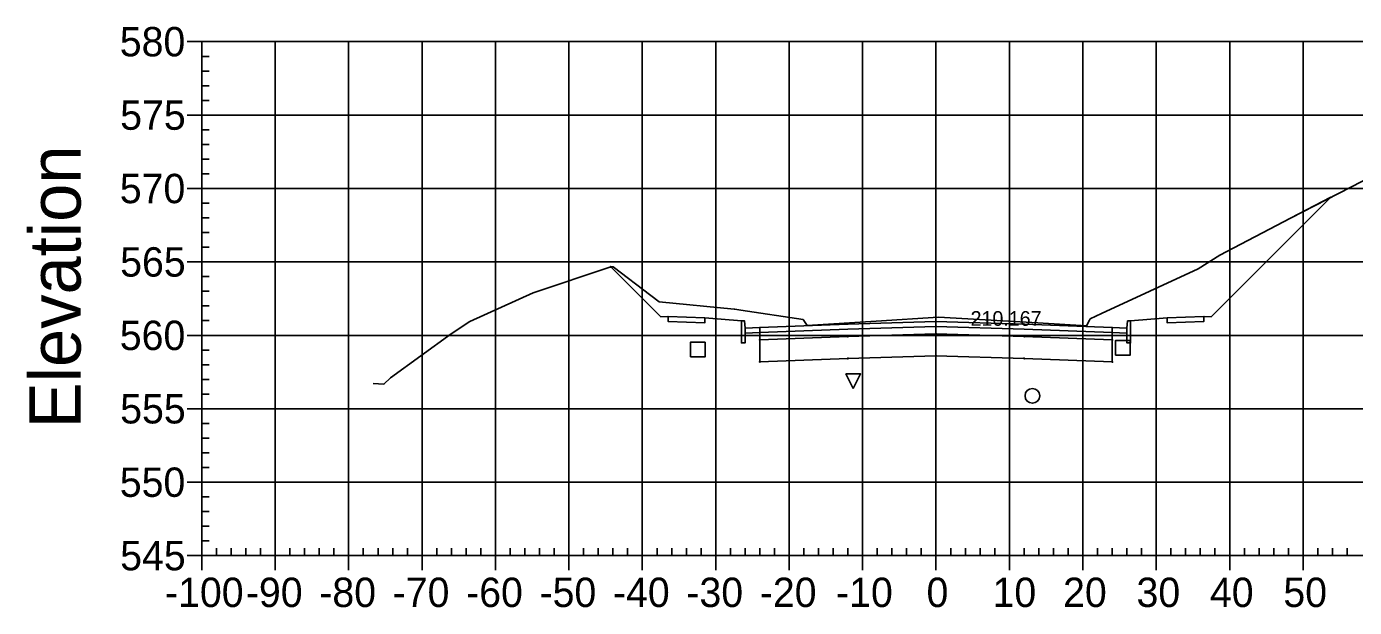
# Model space of a CAD drawing. Extents: x 704834 to 709892, y 372981 to 377533.
# Drawn here: x 706563 to 706743.9, y 373685.8 to 373764.9 of the extents above; entities that cross this region are included whole.
import ezdxf

# ---------------------------------------------------------------- set-up
doc = ezdxf.new("R2010")
doc.units = 0
for name, color, linetype in [('1', 7, 'Continuous'), ('10', 7, 'Continuous'), ('13', 7, 'Continuous'), ('14', 7, 'Continuous'), ('4', 7, 'Continuous'), ('57', 7, 'Continuous'), ('59', 7, 'Continuous'), ('60', 7, 'Continuous'), ('Default_Xsect', 7, 'Continuous'), ('Existing', 7, 'Continuous')]:
    doc.layers.add(name, color=color, linetype=linetype)

msp = doc.modelspace()

# ---------------------------------------------------------------- linework, layer by layer
for points in [[(706724.37, 373725.35), (706740.65, 373741.62)], [(706649.37, 373725.35), (706642.57, 373732.15)], [(706650.37, 373725.39), (706649.37, 373725.35)], [(706660.37, 373724.79), (706655.37, 373725.19)], [(706713.37, 373724.79), (706718.37, 373725.19)], [(706723.37, 373725.39), (706724.37, 373725.35)]]:
    msp.add_lwpolyline(points)
for points in [[(706655.37, 373725.19), (706650.37, 373725.39), (706650.37, 373724.72), (706655.37, 373724.52)], [(706718.37, 373724.52), (706723.37, 373724.72), (706723.37, 373725.39), (706718.37, 373725.19)], [(706660.87, 373723.79), (706660.79, 373724.79), (706660.37, 373724.79), (706660.37, 373721.79), (706660.87, 373721.79)], [(706662.87, 373723.87), (706660.87, 373723.79), (706660.87, 373723.12), (706662.87, 373723.2)], [(706686.87, 373724.04), (706698.87, 373723.68), (706710.87, 373723.2), (706710.87, 373723.87), (706698.87, 373724.35), (706686.87, 373724.71), (706674.87, 373724.35), (706662.87, 373723.87), (706662.87, 373723.2), (706674.87, 373723.68)], [(706686.87, 373723.04), (706698.87, 373722.68), (706710.87, 373722.2), (706710.87, 373723.2), (706698.87, 373723.68), (706686.87, 373724.04), (706674.87, 373723.68), (706662.87, 373723.2), (706662.87, 373722.2), (706674.87, 373722.68)], [(706686.82, 373723.99), (706686.92, 373723.99), (706686.92, 373724.09), (706686.82, 373724.09)], [(706710.87, 373723.2), (706712.87, 373723.12), (706712.87, 373723.79), (706710.87, 373723.87)], [(706712.87, 373721.79), (706713.37, 373721.79), (706713.37, 373724.79), (706712.96, 373724.79), (706712.87, 373723.79)], [(706662.82, 373722.15), (706662.92, 373722.15), (706662.92, 373722.25), (706662.82, 373722.25)], [(706686.87, 373720.04), (706698.87, 373719.68), (706710.87, 373719.2), (706710.87, 373722.2), (706698.87, 373722.68), (706686.87, 373723.04), (706674.87, 373722.68), (706662.87, 373722.2), (706662.87, 373719.2), (706674.87, 373719.68)], [(706674.82, 373722.63), (706674.92, 373722.63), (706674.92, 373722.73), (706674.82, 373722.73)], [(706686.82, 373722.99), (706686.92, 373722.99), (706686.92, 373723.09), (706686.82, 373723.09)], [(706698.82, 373722.63), (706698.92, 373722.63), (706698.92, 373722.73), (706698.82, 373722.73)], [(706710.82, 373722.15), (706710.92, 373722.15), (706710.92, 373722.25), (706710.82, 373722.25)], [(706674.82, 373719.63), (706674.92, 373719.63), (706674.92, 373719.73), (706674.82, 373719.73)], [(706686.82, 373719.99), (706686.92, 373719.99), (706686.92, 373720.09), (706686.82, 373720.09)], [(706698.82, 373719.63), (706698.92, 373719.63), (706698.92, 373719.73), (706698.82, 373719.73)], [(706662.82, 373719.15), (706662.92, 373719.15), (706662.92, 373719.25), (706662.82, 373719.25)], [(706710.82, 373719.15), (706710.92, 373719.15), (706710.92, 373719.25), (706710.82, 373719.25)]]:
    msp.add_lwpolyline(points, close=True)
at = {"layer": '1'}
for points in [[(706642.57, 373732.15), (706642.58, 373732.16), (706642.88, 373732.17), (706648.01, 373728.27), (706649.18, 373727.39), (706659.39, 373726.4), (706659.47, 373726.38), (706660.28, 373726.27), (706668.77, 373724.97), (706668.95, 373724.7), (706669.33, 373724.17), (706678.71, 373724.76), (706687.23, 373725.28), (706700.72, 373724.54), (706707.39, 373724.11), (706707.8, 373724.89), (706707.89, 373725.06), (706709.39, 373725.78), (706722.56, 373731.87), (706725.52, 373733.74), (706735.16, 373738.8), (706740.65, 373741.62), (706724.37, 373725.35), (706723.37, 373725.39), (706723.37, 373724.72), (706718.37, 373724.52), (706718.37, 373725.19), (706713.37, 373724.79), (706713.37, 373721.79), (706712.87, 373721.79), (706712.87, 373723.12), (706710.87, 373723.2), (706710.87, 373722.2), (706710.87, 373719.2), (706698.87, 373719.68), (706686.87, 373720.04), (706674.87, 373719.68), (706662.87, 373719.2), (706662.87, 373722.2), (706662.87, 373723.2), (706660.87, 373723.12), (706660.87, 373721.79), (706660.37, 373721.79), (706660.37, 373724.79), (706655.37, 373725.19), (706655.37, 373724.52), (706650.37, 373724.72), (706650.37, 373725.39), (706649.37, 373725.35)], [(706675.59, 373715.56), (706674.59, 373717.56), (706676.59, 373717.56)]]:
    msp.add_lwpolyline(points, close=True, dxfattribs=at)
at = {"layer": '10'}
msp.add_lwpolyline([(706653.42, 373719.88), (706655.42, 373719.88), (706655.42, 373721.88), (706653.42, 373721.88)], close=True, dxfattribs=at)
at = {"layer": '13'}
msp.add_circle((706700, 373714.58), 1, dxfattribs=at)
at = {"layer": '14'}
for points in [[(706740.65, 373741.62), (706740.65, 373741.67), (706740.65, 373741.62), (706740.6, 373741.62), (706740.65, 373741.62), (706740.65, 373741.57), (706740.65, 373741.62), (706740.7, 373741.62)], [(706642.57, 373732.15), (706642.57, 373732.2), (706642.57, 373732.15), (706642.52, 373732.15), (706642.57, 373732.15), (706642.57, 373732.1), (706642.57, 373732.15), (706642.62, 373732.15)], [(706662.87, 373723.87), (706662.87, 373723.92), (706662.87, 373723.87), (706662.82, 373723.87), (706662.87, 373723.87), (706662.87, 373723.82), (706662.87, 373723.87), (706662.92, 373723.87)], [(706674.87, 373724.35), (706674.87, 373724.4), (706674.87, 373724.35), (706674.82, 373724.35), (706674.87, 373724.35), (706674.87, 373724.3), (706674.87, 373724.35), (706674.92, 373724.35)], [(706686.87, 373724.71), (706686.87, 373724.76), (706686.87, 373724.71), (706686.82, 373724.71), (706686.87, 373724.71), (706686.87, 373724.66), (706686.87, 373724.71), (706686.92, 373724.71)], [(706698.87, 373724.35), (706698.87, 373724.4), (706698.87, 373724.35), (706698.82, 373724.35), (706698.87, 373724.35), (706698.87, 373724.3), (706698.87, 373724.35), (706698.92, 373724.35)], [(706710.87, 373723.87), (706710.87, 373723.92), (706710.87, 373723.87), (706710.82, 373723.87), (706710.87, 373723.87), (706710.87, 373723.82), (706710.87, 373723.87), (706710.92, 373723.87)]]:
    msp.add_lwpolyline(points, dxfattribs=at)
at = {"layer": '4'}
msp.add_lwpolyline([(706711.33, 373720.14), (706713.33, 373720.14), (706713.33, 373722.14), (706711.33, 373722.14)], close=True, dxfattribs=at)
at = {"layer": '57'}
for p, q in [((706584.87, 373762.82), (706586.87, 373762.82)), ((706586.87, 373762.82), (706786.87, 373762.82)), ((706586.87, 373692.82), (706586.87, 373762.82)), ((706586.87, 373692.82), (706586.87, 373762.82)), ((706596.87, 373692.82), (706596.87, 373762.82)), ((706606.87, 373692.82), (706606.87, 373762.82)), ((706616.87, 373692.82), (706616.87, 373762.82)), ((706626.87, 373692.82), (706626.87, 373762.82)), ((706636.87, 373692.82), (706636.87, 373762.82)), ((706646.87, 373692.82), (706646.87, 373762.82)), ((706656.87, 373692.82), (706656.87, 373762.82)), ((706666.87, 373692.82), (706666.87, 373762.82)), ((706676.87, 373692.82), (706676.87, 373762.82)), ((706686.87, 373692.82), (706686.87, 373762.82)), ((706696.87, 373692.82), (706696.87, 373762.82)), ((706706.87, 373692.82), (706706.87, 373762.82)), ((706716.87, 373692.82), (706716.87, 373762.82)), ((706726.87, 373692.82), (706726.87, 373762.82)), ((706736.87, 373692.82), (706736.87, 373762.82)), ((706586.87, 373760.82), (706587.87, 373760.82)), ((706586.87, 373758.82), (706587.87, 373758.82)), ((706586.87, 373756.82), (706587.87, 373756.82)), ((706586.87, 373754.82), (706587.87, 373754.82)), ((706584.87, 373752.82), (706586.87, 373752.82)), ((706586.87, 373752.82), (706786.87, 373752.82)), ((706586.87, 373750.82), (706587.87, 373750.82)), ((706586.87, 373748.82), (706587.87, 373748.82)), ((706586.87, 373746.82), (706587.87, 373746.82)), ((706586.87, 373744.82), (706587.87, 373744.82)), ((706584.87, 373742.82), (706586.87, 373742.82)), ((706586.87, 373742.82), (706786.87, 373742.82)), ((706586.87, 373740.82), (706587.87, 373740.82)), ((706586.87, 373738.82), (706587.87, 373738.82)), ((706586.87, 373736.82), (706587.87, 373736.82)), ((706586.87, 373734.82), (706587.87, 373734.82)), ((706584.87, 373732.82), (706586.87, 373732.82)), ((706586.87, 373732.82), (706786.87, 373732.82)), ((706586.87, 373730.82), (706587.87, 373730.82)), ((706586.87, 373728.82), (706587.87, 373728.82)), ((706586.87, 373726.82), (706587.87, 373726.82)), ((706586.87, 373724.82), (706587.87, 373724.82)), ((706584.87, 373722.82), (706586.87, 373722.82)), ((706586.87, 373722.82), (706786.87, 373722.82)), ((706586.87, 373720.82), (706587.87, 373720.82)), ((706586.87, 373718.82), (706587.87, 373718.82)), ((706586.87, 373716.82), (706587.87, 373716.82)), ((706586.87, 373714.82), (706587.87, 373714.82)), ((706584.87, 373712.82), (706586.87, 373712.82)), ((706586.87, 373712.82), (706786.87, 373712.82)), ((706586.87, 373710.82), (706587.87, 373710.82)), ((706586.87, 373708.82), (706587.87, 373708.82)), ((706586.87, 373706.82), (706587.87, 373706.82)), ((706586.87, 373704.82), (706587.87, 373704.82)), ((706584.87, 373702.82), (706586.87, 373702.82)), ((706586.87, 373702.82), (706786.87, 373702.82)), ((706586.87, 373700.82), (706587.87, 373700.82)), ((706586.87, 373698.82), (706587.87, 373698.82)), ((706586.87, 373696.82), (706587.87, 373696.82)), ((706586.87, 373694.82), (706587.87, 373694.82)), ((706584.87, 373692.82), (706586.87, 373692.82)), ((706586.87, 373692.82), (706786.87, 373692.82)), ((706586.87, 373692.82), (706786.87, 373692.82)), ((706586.87, 373690.82), (706586.87, 373692.82)), ((706588.87, 373692.82), (706588.87, 373693.82)), ((706590.87, 373692.82), (706590.87, 373693.82)), ((706592.87, 373692.82), (706592.87, 373693.82)), ((706594.87, 373692.82), (706594.87, 373693.82)), ((706596.87, 373690.82), (706596.87, 373692.82)), ((706598.87, 373692.82), (706598.87, 373693.82)), ((706600.87, 373692.82), (706600.87, 373693.82)), ((706602.87, 373692.82), (706602.87, 373693.82)), ((706604.87, 373692.82), (706604.87, 373693.82)), ((706606.87, 373690.82), (706606.87, 373692.82)), ((706608.87, 373692.82), (706608.87, 373693.82)), ((706610.87, 373692.82), (706610.87, 373693.82)), ((706612.87, 373692.82), (706612.87, 373693.82)), ((706614.87, 373692.82), (706614.87, 373693.82)), ((706616.87, 373690.82), (706616.87, 373692.82)), ((706618.87, 373692.82), (706618.87, 373693.82)), ((706620.87, 373692.82), (706620.87, 373693.82)), ((706622.87, 373692.82), (706622.87, 373693.82)), ((706624.87, 373692.82), (706624.87, 373693.82)), ((706626.87, 373690.82), (706626.87, 373692.82)), ((706628.87, 373692.82), (706628.87, 373693.82)), ((706630.87, 373692.82), (706630.87, 373693.82)), ((706632.87, 373692.82), (706632.87, 373693.82)), ((706634.87, 373692.82), (706634.87, 373693.82)), ((706636.87, 373690.82), (706636.87, 373692.82)), ((706638.87, 373692.82), (706638.87, 373693.82)), ((706640.87, 373692.82), (706640.87, 373693.82)), ((706642.87, 373692.82), (706642.87, 373693.82)), ((706644.87, 373692.82), (706644.87, 373693.82)), ((706646.87, 373690.82), (706646.87, 373692.82)), ((706648.87, 373692.82), (706648.87, 373693.82)), ((706650.87, 373692.82), (706650.87, 373693.82)), ((706652.87, 373692.82), (706652.87, 373693.82)), ((706654.87, 373692.82), (706654.87, 373693.82)), ((706656.87, 373690.82), (706656.87, 373692.82)), ((706658.87, 373692.82), (706658.87, 373693.82)), ((706660.87, 373692.82), (706660.87, 373693.82)), ((706662.87, 373692.82), (706662.87, 373693.82)), ((706664.87, 373692.82), (706664.87, 373693.82)), ((706666.87, 373690.82), (706666.87, 373692.82)), ((706668.87, 373692.82), (706668.87, 373693.82)), ((706670.87, 373692.82), (706670.87, 373693.82)), ((706672.87, 373692.82), (706672.87, 373693.82)), ((706674.87, 373692.82), (706674.87, 373693.82)), ((706676.87, 373690.82), (706676.87, 373692.82)), ((706678.87, 373692.82), (706678.87, 373693.82)), ((706680.87, 373692.82), (706680.87, 373693.82)), ((706682.87, 373692.82), (706682.87, 373693.82)), ((706684.87, 373692.82), (706684.87, 373693.82)), ((706686.87, 373690.82), (706686.87, 373692.82)), ((706688.87, 373692.82), (706688.87, 373693.82)), ((706690.87, 373692.82), (706690.87, 373693.82)), ((706692.87, 373692.82), (706692.87, 373693.82)), ((706694.87, 373692.82), (706694.87, 373693.82)), ((706696.87, 373690.82), (706696.87, 373692.82)), ((706698.87, 373692.82), (706698.87, 373693.82)), ((706700.87, 373692.82), (706700.87, 373693.82)), ((706702.87, 373692.82), (706702.87, 373693.82)), ((706704.87, 373692.82), (706704.87, 373693.82)), ((706706.87, 373690.82), (706706.87, 373692.82)), ((706708.87, 373692.82), (706708.87, 373693.82)), ((706710.87, 373692.82), (706710.87, 373693.82)), ((706712.87, 373692.82), (706712.87, 373693.82)), ((706714.87, 373692.82), (706714.87, 373693.82)), ((706716.87, 373690.82), (706716.87, 373692.82)), ((706718.87, 373692.82), (706718.87, 373693.82)), ((706720.87, 373692.82), (706720.87, 373693.82)), ((706722.87, 373692.82), (706722.87, 373693.82)), ((706724.87, 373692.82), (706724.87, 373693.82)), ((706726.87, 373690.82), (706726.87, 373692.82)), ((706728.87, 373692.82), (706728.87, 373693.82)), ((706730.87, 373692.82), (706730.87, 373693.82)), ((706732.87, 373692.82), (706732.87, 373693.82)), ((706734.87, 373692.82), (706734.87, 373693.82)), ((706736.87, 373690.82), (706736.87, 373692.82)), ((706738.87, 373692.82), (706738.87, 373693.82)), ((706740.87, 373692.82), (706740.87, 373693.82)), ((706742.87, 373692.82), (706742.87, 373693.82))]:
    msp.add_line(p, q, dxfattribs=at)
at = {"layer": 'Default_Xsect'}
msp.add_lwpolyline([(706642.57, 373732.15), (706649.37, 373725.35), (706650.37, 373725.39), (706655.37, 373725.19), (706660.37, 373724.79), (706660.79, 373724.79), (706660.87, 373723.79), (706662.87, 373723.87), (706674.87, 373724.35), (706686.87, 373724.71), (706698.87, 373724.35), (706710.87, 373723.87), (706712.87, 373723.79), (706712.96, 373724.79), (706713.37, 373724.79), (706718.37, 373725.19), (706723.37, 373725.39), (706724.37, 373725.35), (706740.65, 373741.62)], dxfattribs=at)
at = {"layer": 'Existing'}
msp.add_lwpolyline([(706610.2, 373716.25), (706611.67, 373716.16), (706612.56, 373717.02), (706620.84, 373723.03), (706623.39, 373724.71), (706632.01, 373728.63), (706642.58, 373732.16), (706642.88, 373732.17), (706648.01, 373728.27), (706649.18, 373727.39), (706659.39, 373726.4), (706659.47, 373726.38), (706660.28, 373726.27), (706668.77, 373724.97), (706668.95, 373724.7), (706669.33, 373724.17), (706678.71, 373724.76), (706687.23, 373725.28), (706700.72, 373724.54), (706707.39, 373724.11), (706707.8, 373724.89), (706707.89, 373725.06), (706709.39, 373725.78), (706722.56, 373731.87), (706725.52, 373733.74), (706735.16, 373738.8), (706751.49, 373747.19)], dxfattribs=at)

# ---------------------------------------------------------------- texts
at = {"layer": '14'}
for p in [(706650.34, 373725.34), (706723.34, 373725.34), (706650.34, 373724.67), (706655.34, 373724.47), (706718.34, 373724.47), (706723.34, 373724.67)]:
    msp.add_text('+', height=0.1, dxfattribs=at).set_placement(p)
at = {"layer": '57'}
for s, p in [('580', (706575.7, 373760.82)), ('575', (706575.75, 373750.82)), ('570', (706575.7, 373740.82)), ('565', (706575.75, 373730.82)), ('560', (706575.7, 373720.82)), ('555', (706575.75, 373710.82)), ('550', (706575.7, 373700.82)), ('545', (706575.75, 373690.82)), ('-100', (706581.86, 373685.82)), ('-90', (706592.87, 373685.82)), ('-80', (706602.87, 373685.82)), ('-70', (706612.87, 373685.82)), ('-60', (706622.87, 373685.82)), ('-50', (706632.87, 373685.82)), ('-40', (706642.87, 373685.82)), ('-30', (706652.87, 373685.82)), ('-20', (706662.87, 373685.82)), ('-10', (706673.26, 373685.82)), ('0', (706685.58, 373685.82)), ('10', (706694.57, 373685.82)), ('20', (706704.18, 373685.82)), ('30', (706714.18, 373685.82)), ('40', (706724.18, 373685.82)), ('50', (706734.18, 373685.82))]:
    msp.add_text(s, height=4, dxfattribs=at).set_placement(p)
at = {"layer": '59'}
msp.add_text('210.167', height=2, dxfattribs=at).set_placement((706691.58, 373724.12))
at = {"layer": '60'}
msp.add_text('Elevation', height=7, rotation=90, dxfattribs=at).set_placement((706570.37, 373710.18))

doc.saveas('drawing.dxf')
